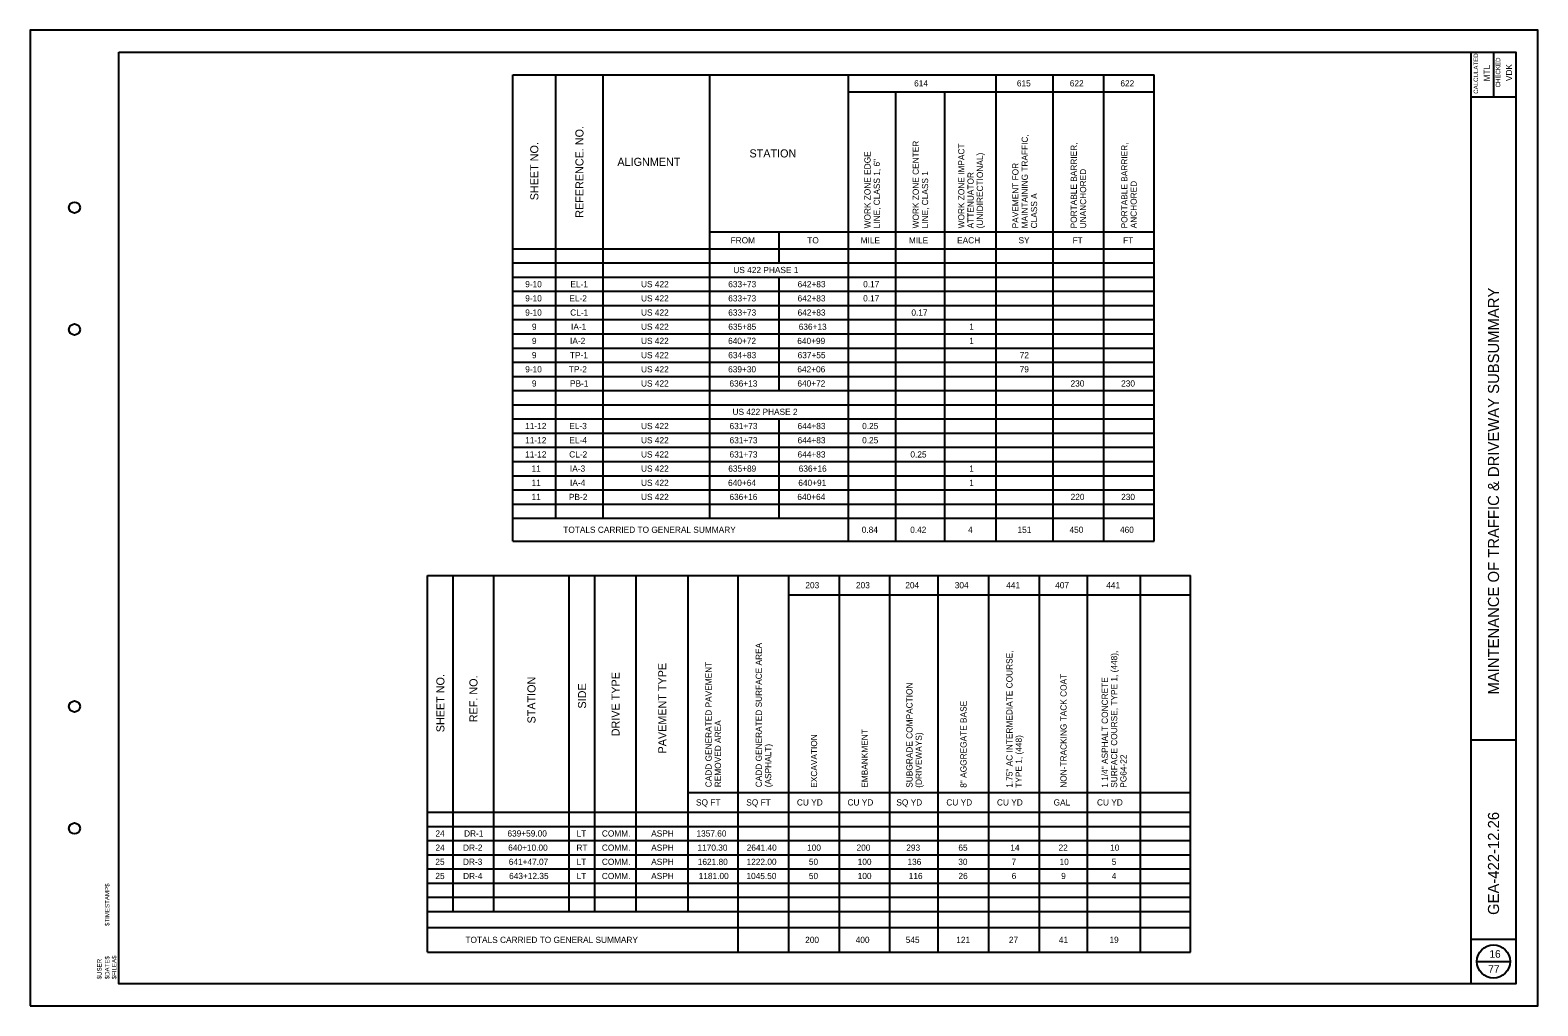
# Model space of a CAD drawing. Extents: x 0 to 34, y 0 to 22.
import ezdxf

# ---------------------------------------------------------------- set-up
doc = ezdxf.new("R2010")
doc.units = 0
for name, color, linetype in [('SH_Border', 7, 'Continuous'), ('SH_Cut_Line', 7, 'Continuous'), ('SH_Data', 7, 'Continuous'), ('SH_Text', 7, 'Continuous')]:
    doc.layers.add(name, color=color, linetype=linetype)

msp = doc.modelspace()

# ---------------------------------------------------------------- linework, layer by layer
at = {"layer": 'SH_Border'}
for p, q in [((32.5, 0.5), (32.5, 21.5)), ((33, 21.5), (33, 20.5)), ((32.5, 20.5), (33.5, 20.5)), ((32.5, 6), (33.5, 6)), ((32.5, 1.5), (33.5, 1.5))]:
    msp.add_line(p, q, dxfattribs=at)
msp.add_lwpolyline([(2, 21.5), (33.5, 21.5), (33.5, 0.5), (2, 0.5)], close=True, dxfattribs=at)
for centre in [(1, 18), (1, 15.25), (1, 6.75), (1, 4)]:
    msp.add_circle(centre, 0.125, dxfattribs=at)
at = {"layer": 'SH_Cut_Line'}
msp.add_lwpolyline([(0, 0), (34, 0), (34, 22), (0, 22)], close=True, dxfattribs=at)
at = {"layer": 'SH_Data'}
msp.add_line((32.625, 1), (33.375, 1), dxfattribs=at)
msp.add_circle((33, 1), 0.375, dxfattribs=at)
at = {"layer": 'SH_Text'}
for p, q in [((10.886, 20.991), (10.886, 20.991)), ((10.886, 20.991), (25.35, 20.991)), ((10.886, 10.475), (10.886, 20.991)), ((11.851, 10.995), (11.851, 20.991)), ((12.922, 10.995), (12.922, 20.991)), ((15.327, 10.995), (15.327, 20.991)), ((18.452, 10.475), (18.452, 20.991)), ((21.787, 10.475), (21.787, 20.991)), ((23.068, 10.475), (23.068, 20.991)), ((24.209, 10.475), (24.209, 20.991)), ((25.35, 10.475), (25.35, 20.991)), ((18.452, 20.611), (25.35, 20.611)), ((19.522, 10.475), (19.522, 20.611)), ((20.628, 10.475), (20.628, 20.611)), ((15.327, 17.452), (25.35, 17.452)), ((16.889, 16.752), (16.889, 17.452)), ((10.886, 17.072), (25.35, 17.072)), ((10.886, 16.752), (25.35, 16.752)), ((10.886, 16.433), (25.35, 16.433)), ((16.889, 13.874), (16.889, 16.433)), ((10.886, 16.113), (25.35, 16.113)), ((10.886, 15.793), (25.35, 15.793)), ((10.886, 15.473), (25.35, 15.473)), ((10.886, 15.153), (25.35, 15.153)), ((10.886, 14.833), (25.35, 14.833)), ((10.886, 14.513), (25.35, 14.513)), ((10.886, 14.193), (25.35, 14.193)), ((10.886, 13.874), (25.35, 13.874)), ((10.886, 13.554), (25.35, 13.554)), ((10.886, 13.234), (25.35, 13.234)), ((16.889, 10.995), (16.889, 13.234)), ((10.886, 12.914), (25.35, 12.914)), ((10.886, 12.594), (25.35, 12.594)), ((10.886, 12.274), (25.35, 12.274)), ((10.886, 11.954), (25.35, 11.954)), ((10.886, 11.634), (25.35, 11.634)), ((10.886, 11.315), (25.35, 11.315)), ((10.886, 10.995), (25.35, 10.995)), ((10.886, 10.475), (25.35, 10.475)), ((8.962, 9.705), (8.962, 9.705)), ((8.962, 9.705), (26.164, 9.705)), ((8.962, 1.208), (8.962, 9.705)), ((9.541, 2.128), (9.541, 9.705)), ((10.454, 2.128), (10.454, 9.705)), ((12.157, 2.128), (12.157, 9.705)), ((12.736, 2.128), (12.736, 9.705)), ((13.666, 2.128), (13.666, 9.705)), ((14.842, 2.128), (14.842, 9.705)), ((15.966, 1.208), (15.966, 9.705)), ((17.107, 1.208), (17.107, 9.705)), ((18.248, 1.208), (18.248, 9.705)), ((19.389, 1.208), (19.389, 9.705)), ((20.477, 1.208), (20.477, 9.705)), ((21.618, 1.208), (21.618, 9.705)), ((22.759, 1.208), (22.759, 9.705)), ((23.847, 1.208), (23.847, 9.705)), ((25.041, 1.208), (25.041, 9.705)), ((26.164, 1.208), (26.164, 9.705)), ((17.107, 9.265), (26.164, 9.265)), ((14.842, 4.807), (26.164, 4.807)), ((8.962, 4.367), (26.164, 4.367)), ((8.962, 4.047), (26.164, 4.047)), ((8.962, 3.727), (26.164, 3.727)), ((8.962, 3.407), (26.164, 3.407)), ((8.962, 3.088), (26.164, 3.088)), ((8.962, 2.768), (26.164, 2.768)), ((8.962, 2.448), (26.164, 2.448)), ((8.962, 2.128), (26.164, 2.128)), ((8.962, 1.768), (26.164, 1.768)), ((8.962, 1.208), (26.164, 1.208))]:
    msp.add_line(p, q, dxfattribs=at)

# ---------------------------------------------------------------- texts
at = {"layer": 'SH_Data'}
for s, height, rotation, p in [('CALCULATED', 0.1, 90, (32.652, 20.565)), ('MTL', 0.14, 90, (32.92, 20.844)), ('CHECKED', 0.1, 90, (33.152, 20.708)), ('VDK', 0.14, 90, (33.42, 20.851)), ('MAINTENANCE OF TRAFFIC & DRIVEWAY SUBSUMMARY', 0.25, 90, (33.125, 7.02)), (' GEA-422-12.26 ', 0.25, 90, (33.125, 1.957)), ('$TIMESTAMP$', 0.1, 89.9931, (1.788, 1.8)), ('$USER', 0.1, 89.9931, (1.611, 0.598)), ('$DATE$', 0.1, 89.9931, (1.788, 0.598)), ('$FILEA$', 0.1, 89.9931, (1.944, 0.598))]:
    msp.add_text(s, height=height, rotation=rotation, dxfattribs=at).set_placement(p)
for s, p in [('16', (32.908, 1.085)), ('77', (32.882, 0.745))]:
    msp.add_text(s, height=0.17, dxfattribs=at).set_placement(p)
at = {"layer": 'SH_Text'}
for s, height, p in [('614', 0.14, (19.934, 20.731)), ('615', 0.14, (22.252, 20.731)), ('622', 0.14, (23.445, 20.731)), ('622', 0.14, (24.586, 20.731)), ('ALIGNMENT', 0.182, (13.243, 18.94)), ('STATION', 0.182, (16.222, 19.13)), ('FROM', 0.14, (15.796, 17.192)), ('TO', 0.14, (17.525, 17.192)), ('MILE', 0.14, (18.728, 17.192)), ('MILE', 0.14, (19.816, 17.192)), ('EACH', 0.14, (20.904, 17.192)), ('SY', 0.14, (22.288, 17.192)), ('FT', 0.14, (23.507, 17.192)), ('FT', 0.14, (24.648, 17.192)), ('US 422 PHASE 1', 0.14, (15.858, 16.522)), ('9-10', 0.14, (11.164, 16.203)), ('EL-1', 0.14, (12.183, 16.203)), ('US 422', 0.14, (13.776, 16.203)), ('633+73', 0.14, (15.743, 16.203)), ('642+83', 0.14, (17.307, 16.203)), ('0.17', 0.14, (18.785, 16.203)), ('9-10', 0.14, (11.164, 15.883)), ('EL-2', 0.14, (12.16, 15.883)), ('US 422', 0.14, (13.776, 15.883)), ('633+73', 0.14, (15.743, 15.883)), ('642+83', 0.14, (17.307, 15.883)), ('0.17', 0.14, (18.785, 15.883)), ('9-10', 0.14, (11.164, 15.563)), ('CL-1', 0.14, (12.179, 15.563)), ('US 422', 0.14, (13.776, 15.563)), ('633+73', 0.14, (15.743, 15.563)), ('642+83', 0.14, (17.307, 15.563)), ('0.17', 0.14, (19.873, 15.563)), ('9', 0.14, (11.316, 15.243)), ('IA-1', 0.14, (12.198, 15.243)), ('US 422', 0.14, (13.776, 15.243)), ('635+85', 0.14, (15.744, 15.243)), ('636+13', 0.14, (17.332, 15.243)), ('1', 0.14, (21.178, 15.243)), ('9', 0.14, (11.316, 14.923)), ('IA-2', 0.14, (12.175, 14.923)), ('US 422', 0.14, (13.776, 14.923)), ('640+72', 0.14, (15.74, 14.923)), ('640+99', 0.14, (17.3, 14.923)), ('1', 0.14, (21.178, 14.923)), ('9', 0.14, (11.316, 14.603)), ('TP-1', 0.14, (12.173, 14.603)), ('US 422', 0.14, (13.776, 14.603)), ('634+83', 0.14, (15.743, 14.603)), ('637+55', 0.14, (17.307, 14.603)), ('72', 0.14, (22.316, 14.603)), ('9-10', 0.14, (11.164, 14.283)), ('TP-2', 0.14, (12.149, 14.283)), ('US 422', 0.14, (13.776, 14.283)), ('639+30', 0.14, (15.74, 14.283)), ('642+06', 0.14, (17.301, 14.283)), ('79', 0.14, (22.315, 14.283)), ('9', 0.14, (11.316, 13.964)), ('PB-1', 0.14, (12.174, 13.964)), ('US 422', 0.14, (13.776, 13.964)), ('636+13', 0.14, (15.77, 13.964)), ('640+72', 0.14, (17.302, 13.964)), ('230', 0.14, (23.462, 13.964)), ('230', 0.14, (24.603, 13.964)), ('US 422 PHASE 2', 0.14, (15.839, 13.324)), ('11-12', 0.14, (11.163, 13.004)), ('EL-3', 0.14, (12.158, 13.004)), ('US 422', 0.14, (13.776, 13.004)), ('631+73', 0.14, (15.772, 13.004)), ('644+83', 0.14, (17.306, 13.004)), ('0.25', 0.14, (18.762, 13.004)), ('11-12', 0.14, (11.163, 12.684)), ('EL-4', 0.14, (12.16, 12.684)), ('US 422', 0.14, (13.776, 12.684)), ('631+73', 0.14, (15.772, 12.684)), ('644+83', 0.14, (17.306, 12.684)), ('0.25', 0.14, (18.762, 12.684)), ('11-12', 0.14, (11.163, 12.364)), ('CL-2', 0.14, (12.156, 12.364)), ('US 422', 0.14, (13.776, 12.364)), ('631+73', 0.14, (15.772, 12.364)), ('644+83', 0.14, (17.306, 12.364)), ('0.25', 0.14, (19.85, 12.364)), ('11', 0.14, (11.307, 12.044)), ('IA-3', 0.14, (12.173, 12.044)), ('US 422', 0.14, (13.776, 12.044)), ('635+89', 0.14, (15.744, 12.044)), ('636+16', 0.14, (17.332, 12.044)), ('1', 0.14, (21.178, 12.044)), ('11', 0.14, (11.307, 11.724)), ('IA-4', 0.14, (12.175, 11.724)), ('US 422', 0.14, (13.776, 11.724)), ('640+64', 0.14, (15.738, 11.724)), ('640+91', 0.14, (17.323, 11.724)), ('1', 0.14, (21.178, 11.724)), ('11', 0.14, (11.307, 11.405)), ('PB-2', 0.14, (12.15, 11.405)), ('US 422', 0.14, (13.776, 11.405)), ('636+16', 0.14, (15.77, 11.405)), ('640+64', 0.14, (17.301, 11.405)), ('220', 0.14, (23.464, 11.405)), ('230', 0.14, (24.603, 11.405)), ('TOTALS CARRIED TO GENERAL SUMMARY', 0.14, (12.022, 10.665)), ('0.84', 0.14, (18.753, 10.665)), ('0.42', 0.14, (19.846, 10.665)), ('4', 0.14, (21.151, 10.665)), ('151', 0.14, (22.266, 10.665)), ('450', 0.14, (23.438, 10.665)), ('460', 0.14, (24.577, 10.665)), ('203', 0.14, (17.482, 9.415)), ('203', 0.14, (18.623, 9.415)), ('204', 0.14, (19.736, 9.415)), ('304', 0.14, (20.851, 9.415)), ('441', 0.14, (22.012, 9.415)), ('407', 0.14, (23.115, 9.415)), ('441', 0.14, (24.268, 9.415)), ('SQ FT', 0.14, (15.016, 4.517)), ('SQ FT', 0.14, (16.149, 4.517)), ('CU YD', 0.14, (17.291, 4.517)), ('CU YD', 0.14, (18.432, 4.517)), ('SQ YD', 0.14, (19.534, 4.517)), ('CU YD', 0.14, (20.661, 4.517)), ('CU YD', 0.14, (21.802, 4.517)), ('GAL', 0.14, (23.08, 4.517)), ('CU YD', 0.14, (24.058, 4.517)), ('24', 0.14, (9.14, 3.817)), ('DR-1', 0.14, (9.785, 3.817)), ('639+59.00', 0.14, (10.763, 3.817)), ('LT', 0.14, (12.324, 3.817)), ('COMM.', 0.14, (12.893, 3.817)), ('ASPH', 0.14, (14.005, 3.817)), ('1357.60', 0.14, (15.026, 3.817)), ('24', 0.14, (9.14, 3.497)), ('DR-2', 0.14, (9.762, 3.497)), ('640+10.00', 0.14, (10.781, 3.497)), ('RT', 0.14, (12.32, 3.497)), ('COMM.', 0.14, (12.893, 3.497)), ('ASPH', 0.14, (14.005, 3.497)), ('1170.30', 0.14, (15.049, 3.497)), ('2641.40', 0.14, (16.159, 3.497)), ('100', 0.14, (17.521, 3.497)), ('200', 0.14, (18.636, 3.497)), ('293', 0.14, (19.758, 3.497)), ('65', 0.14, (20.932, 3.497)), ('14', 0.14, (22.104, 3.497)), ('22', 0.14, (23.191, 3.497)), ('10', 0.14, (24.355, 3.497)), ('25', 0.14, (9.138, 3.178)), ('DR-3', 0.14, (9.76, 3.178)), ('641+47.07', 0.14, (10.793, 3.178)), ('LT', 0.14, (12.324, 3.178)), ('COMM.', 0.14, (12.893, 3.178)), ('ASPH', 0.14, (14.005, 3.178)), ('1621.80', 0.14, (15.055, 3.178)), ('1222.00', 0.14, (16.156, 3.178)), ('50', 0.14, (17.561, 3.178)), ('100', 0.14, (18.662, 3.178)), ('136', 0.14, (19.784, 3.178)), ('30', 0.14, (20.93, 3.178)), ('7', 0.14, (22.132, 3.178)), ('10', 0.14, (23.214, 3.178)), ('5', 0.14, (24.391, 3.178)), ('25', 0.14, (9.138, 2.858)), ('DR-4', 0.14, (9.763, 2.858)), ('643+12.35', 0.14, (10.801, 2.858)), ('LT', 0.14, (12.324, 2.858)), ('COMM.', 0.14, (12.893, 2.858)), ('ASPH', 0.14, (14.005, 2.858)), ('1181.00', 0.14, (15.076, 2.858)), ('1045.50', 0.14, (16.153, 2.858)), ('50', 0.14, (17.561, 2.858)), ('100', 0.14, (18.662, 2.858)), ('116', 0.14, (19.813, 2.858)), ('26', 0.14, (20.934, 2.858)), ('6', 0.14, (22.134, 2.858)), ('9', 0.14, (23.25, 2.858)), ('4', 0.14, (24.392, 2.858)), ('TOTALS CARRIED TO GENERAL SUMMARY', 0.14, (9.816, 1.418)), ('200', 0.14, (17.477, 1.418)), ('400', 0.14, (18.617, 1.418)), ('545', 0.14, (19.745, 1.418)), ('121', 0.14, (20.885, 1.418)), ('27', 0.14, (22.072, 1.418)), ('41', 0.14, (23.198, 1.418)), ('19', 0.14, (24.339, 1.418))]:
    msp.add_text(s, height=height, dxfattribs=at).set_placement(p)
for s, height, p in [('REFERENCE. NO.', 0.182, (12.478, 17.77)), ('SHEET NO.', 0.182, (11.46, 18.164)), ('WORK ZONE CENTER', 0.14, (20.04, 17.531)), ('WORK ZONE IMPACT', 0.14, (21.068, 17.531)), ('MAINTAINING TRAFFIC,', 0.14, (22.498, 17.531)), ('PORTABLE BARRIER,', 0.14, (23.604, 17.531)), ('PORTABLE BARRIER,', 0.14, (24.745, 17.531)), ('WORK ZONE EDGE', 0.14, (18.952, 17.531)), ('LINE, CLASS 1, 6"', 0.14, (19.162, 17.531)), ('(UNIDIRECTIONAL)', 0.14, (21.488, 17.531)), ('LINE, CLASS 1', 0.14, (20.25, 17.531)), ('ATTENUATOR', 0.14, (21.278, 17.531)), ('PAVEMENT FOR', 0.14, (22.288, 17.531)), ('UNANCHORED', 0.14, (23.814, 17.531)), ('ANCHORED', 0.14, (24.955, 17.531)), ('CLASS A', 0.14, (22.708, 17.531)), ('CADD GENERATED SURFACE AREA', 0.14, (16.501, 4.929)), ('1.75" AC INTERMEDIATE COURSE,', 0.14, (22.153, 4.918)), ('SURFACE COURSE, TYPE 1, (448),', 0.14, (24.514, 4.918)), ('DRIVE TYPE', 0.182, (13.292, 6.078)), ('PAVEMENT TYPE', 0.182, (14.345, 5.69)), ('CADD GENERATED PAVEMENT', 0.14, (15.369, 4.929)), ('NON-TRACKING TACK COAT', 0.14, (23.373, 4.918)), ('SHEET NO.', 0.182, (9.342, 6.169)), ('REF. NO.', 0.182, (10.088, 6.395)), ('STATION', 0.182, (11.396, 6.368)), ('SIDE', 0.182, (12.537, 6.704)), ('SUBGRADE COMPACTION', 0.14, (19.898, 4.918)), ('1 1/4" ASPHALT CONCRETE', 0.14, (24.304, 4.918)), ('8" AGGREGATE BASE', 0.14, (21.117, 4.918)), ('REMOVED AREA', 0.14, (15.579, 4.929)), ('EMBANKMENT', 0.14, (18.888, 4.918)), ('(DRIVEWAYS) ', 0.14, (20.108, 4.918)), ('(ASPHALT)', 0.14, (16.711, 4.929)), ('EXCAVATION', 0.14, (17.747, 4.918)), ('TYPE 1, (448)', 0.14, (22.363, 4.918)), ('PG64-22', 0.14, (24.724, 4.918))]:
    msp.add_text(s, height=height, rotation=90, dxfattribs=at).set_placement(p)

doc.saveas('drawing.dxf')
